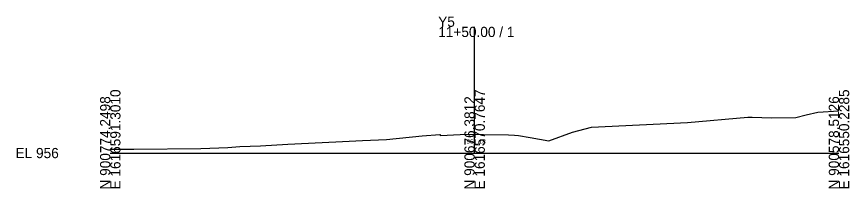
# Model space of a CAD drawing. Extents: x -26 to 1403, y -10 to 4517.
# Drawn here: x -25.7 to 202.8, y 1490.3 to 1537.5 of the extents above; entities that cross this region are included whole.
import ezdxf

# ---------------------------------------------------------------- set-up
doc = ezdxf.new("R2010")
doc.units = 0
for name, color, linetype in [('Exist Cross Section Cell', 7, 'Continuous'), ('Exist XS Center Line Elevation Label', 7, 'Continuous'), ('Exist XS Ground Line', 7, 'Continuous')]:
    doc.layers.add(name, color=color, linetype=linetype)

msp = doc.modelspace()

# ---------------------------------------------------------------- linework, layer by layer
at = {"layer": 'Exist Cross Section Cell'}
for p, q in [((100, 1500), (100, 1534.67)), ((0, 1500), (100, 1500)), ((100, 1500), (200, 1500))]:
    msp.add_line(p, q, dxfattribs=at)
at = {"layer": 'Exist XS Ground Line'}
for p, q in [((190.96, 1510.48), (194.2, 1511.22)), ((194.2, 1511.22), (200, 1511.56)), ((132.11, 1507.12), (158.41, 1508.36)), ((158.41, 1508.36), (174.94, 1509.89)), ((174.94, 1509.89), (176.14, 1509.83)), ((176.14, 1509.83), (181.51, 1509.71)), ((181.51, 1509.71), (188.19, 1509.76)), ((188.19, 1509.76), (190.96, 1510.48)), ((126.86, 1505.76), (132.11, 1507.12)), ((75.84, 1503.74), (85.63, 1504.76)), ((85.63, 1504.76), (90.42, 1505.06)), ((90.42, 1505.06), (90.61, 1504.84)), ((90.61, 1504.84), (96.03, 1505.08)), ((96.03, 1505.08), (100.14, 1505.19)), ((100.14, 1505.19), (102.45, 1505.14)), ((102.45, 1505.14), (109.33, 1505.02)), ((109.33, 1505.02), (110.97, 1504.93)), ((110.97, 1504.93), (112.06, 1504.85)), ((112.06, 1504.85), (115.22, 1504.28)), ((115.22, 1504.28), (120.4, 1503.36)), ((120.4, 1503.36), (126.86, 1505.76)), ((24.86, 1501.26), (32.25, 1501.55)), ((32.25, 1501.55), (35.52, 1501.76)), ((35.52, 1501.76), (41.27, 1502.03)), ((41.27, 1502.03), (48.71, 1502.46)), ((48.71, 1502.46), (61.94, 1503.09)), ((61.94, 1503.09), (69.22, 1503.43)), ((69.22, 1503.43), (75.84, 1503.74)), ((0, 1501.05), (6.48, 1501.09)), ((6.48, 1501.09), (24.86, 1501.26))]:
    msp.add_line(p, q, dxfattribs=at)

# ---------------------------------------------------------------- texts
at = {"layer": 'Exist Cross Section Cell'}
for s, p in [('Y5', (90, 1534.67)), ('11+50.00 / 1', (90, 1531.87)), ('EL 956', (-26, 1498.6))]:
    msp.add_text(s, height=2.8, dxfattribs=at).set_placement(p)
for s, p in [('N 900774.2498', (0, 1490)), ('E 1616591.3010', (2.8, 1490)), ('N 900676.3812', (100, 1490)), ('E 1616570.7647', (102.8, 1490)), ('N 900578.5126', (200, 1490)), ('E 1616550.2285', (202.8, 1490))]:
    msp.add_text(s, height=2.8, rotation=90, dxfattribs=at).set_placement(p)
at = {"layer": 'Exist XS Center Line Elevation Label'}
msp.add_text('961.18', height=1.25, dxfattribs=at).set_placement((97.78, 1502.56))

doc.saveas('drawing.dxf')
